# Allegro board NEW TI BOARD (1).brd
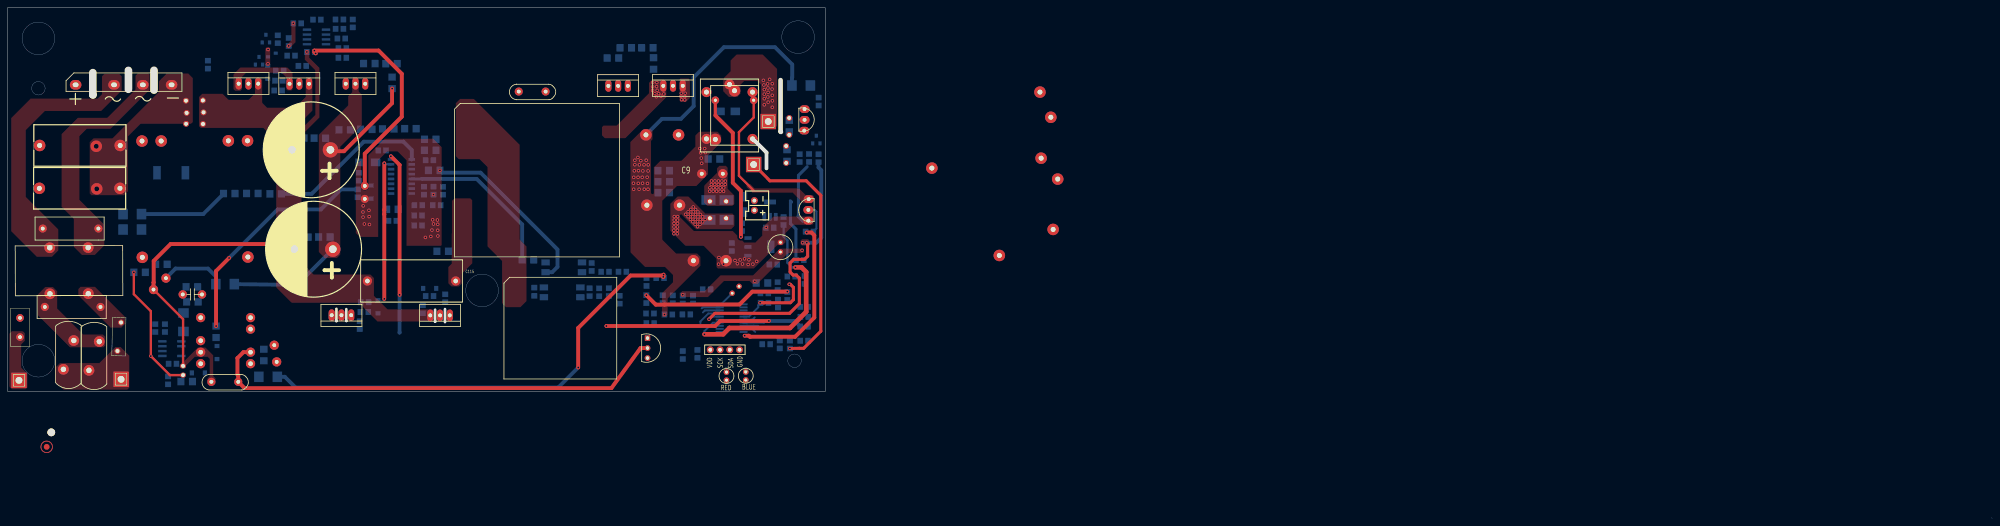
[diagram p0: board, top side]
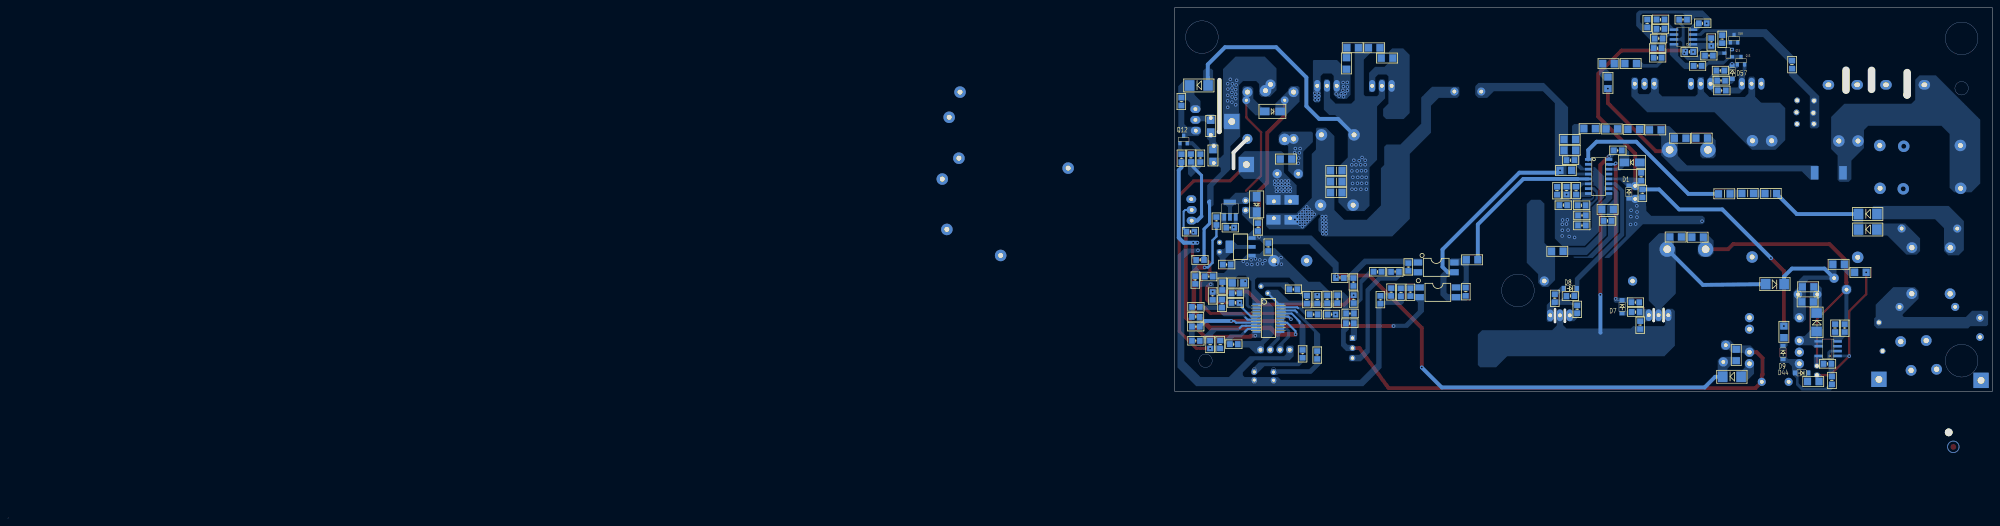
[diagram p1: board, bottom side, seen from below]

Outline 517.07 x 133.07 mm; copper layers: TOP, BOTTOM. Coordinates in mm from the lower left corner of the outline.
Outline path: circle c8,125.07 r4.25 ; circle c8,112.07 r1.75 ; circle c8,41.07 r4.25 ; circle c123.6,59.39 r4.25 ; circle c187.25,38.82 r0.5 ; circle c187.25,35.6 r0.5 ; circle c192.28,38.82 r0.5 ; circle c192.28,35.62 r0.5 ; circle c205,41.07 r1.75 ; circle c205.93,125.4 r4.25 ; 0,133.07 0,33.07 213,33.07 213,133.07 0,133.07 ; 0,133.07 0,33.07 213,33.07 213,133.07 3.74,133.07 3.74,133.07 0,133.07 ; 22.19,116.13 22.19,110.36 22.21,110.34 ; 31.46,116.71 31.46,111.81 ; 38.12,116.75 38.12,111.59 ; 85.66,54.59 85.66,51.41 85.65,51.4 ; 88.23,54.5 88.23,51.46 88.21,51.44 ; 111.37,54.36 111.37,51.26 111.36,51.25 ; 113.94,54.51 113.94,51.15 ; 194.4,98.48 194.54,98.48 197.7,95.32 197.7,91.21 ; 201.36,114.18 201.36,100.8 201.46,100.7 ; 517.07,0 516.79,0.15

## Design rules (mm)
constraint set DEFAULT: min track width 0.127

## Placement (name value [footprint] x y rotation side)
BR1  GBU1010/1000V/10A  [GBI25M]  17.71 112.97 0 top
C4  1nF/250V/1206  [1206ERD]  159.59 122.62 0 bottom
C5  1000uF/80V/TH  [CAP8_5MM18_5]  166.29 99.92 0 top
C6  1000uF/80V/TH  [CAP8_5MM18_5]  166.53 81.6 0 top
C7  2.2uf/450v  [CAP2_4MM5]  45.69 38.53 0 top
C9  100uF/100V/TH  [CAP5_5MM10_5MM]  183.58 89.79 0 top
C10  100nF/100V/0805  [1206ERD]  182.57 93.63 0 bottom
C14  1nF/250V/1206  [1206ERD]  168.11 122.62 180 bottom
C17  100uF/63V/TH  [CAP3_4MM8_5]  93.04 84.93 90 top
C19  0.47uF/50V/0805  [0805ERD]  97.59 95.88 180 bottom
C21  0805  [0805ERD]  156.63 58.94 90 bottom
C24  10nF/25V/0805  [0805ERD]  109.92 93.33 180 bottom
C25  1uF/50V/0805  [0805ERD]  91.18 84.71 270 bottom
C26  1nF/50V/1206  [0805ERD#2]  137.19 59.07 270 bottom
C30  100nF/100V/0805  [0805ERD]  170.65 57.14 270 bottom
C31  100nF/100V/0805  [0805ERD]  178.56 57.02 270 bottom
C32  10uF/1206  [C1206]  195.08 61.34 0 bottom
C33  100nF/0805  [0805ERD]  197.12 58.67 0 bottom
C34  100nF/100V/0805  [0805ERD]  197.16 56.15 0 bottom
C35  100nF/100V/0805  [0805ERD]  207.53 52.49 0 bottom
C36  100nF/100V/0805  [0805ERD]  207.49 49.97 0 bottom
C37  100nF/0805  [0805ERD]  197.64 45.38 180 bottom
C51  470uF/6.3V/TH  [CAP_2_5MM_6_5MM]  201.33 69.41 90 top
C52  100nF/100V/0805  [0805ERD]  199.5 66.13 180 bottom
C53  100nF/100V/0805  [0805ERD]  188.65 70.72 270 bottom
C55  100nF/50V/0805  [0805ERD]  155.61 64.23 0 bottom
C56  100nF/1KV/TH  [1206ERD]  111.88 69.6 0 bottom
C60  680nF 630V  [MPC_21MM_22MM]  8.32 97.16 0 top
C61  680nF/630V  [MPC_21MM_22MM]  8.25 86 0 top
C64  0805 472pF 50V  [0805ERD]  86.9 125.03 0 bottom
C81  220uF 450V  [CAP_10MM_25MM_1KW]  84.08 96.03 180 top
C82  220uF 450V  [CAP_10MM_25MM_1KW]  84.7 70.13 180 top
C106  0805 104pF 50V  [0805ERD]  73.23 124.15 270 bottom
C110  222/ I KV  [CAPY5MMPITCH]  50.62 58.35 180 top
C112  10uf/63V  [CAP4_4MM8_5]  69.77 42.94 98.3 top
C113  222/ I KV  [CAPY7MMPITCH]  53.07 35.57 0 top
C114  4.5uF450V  [CAP4_4MM8_5]  39.61 61.1 222.6 top
C115  100nF/1KV/TH  [BOXCAP_23MM]  116.73 61.85 180 top
C116  1nF/50V/0805  [0805ERD]  100.27 77.52 180 bottom
C117  1nF/50V/0805  [0805ERD]  106.91 76.32 0 bottom
C118  1nF/50V/0805  [0805ERD]  111.77 81.59 0 bottom
C121  22nF 500V  [0805ERD]  70.37 124.88 270 bottom
C122  22nF 500V  [0805ERD]  80.59 129.95 180 bottom
C123  22nF 500V  [0805ERD]  86.43 127.55 0 bottom
C124  22nF 500V  [0805ERD]  89.91 128.99 270 bottom
C125  22nF 500V  [0805ERD]  78.95 121.53 0 bottom
C126  1nF/50V/0805  [0805ERD]  113.41 85.39 270 bottom
C127  1000uF/80V/TH  [CAP8_5MM18_5]  178.66 67.13 0 top
CX1  0.22uF 275V  [CAPBOX14_5MMNEW]  24.18 55.09 180 top
CX2  NC  [CAPBOX14_5MMNEW]  23.63 75.52 180 top
CY3  2K2uF/250V/TH  [CAPY7MMPITCH]  133.15 111.22 0 top
D1  BZT52C16V/SOD-123  [DIODE_SOD123]  94.69 86.73 270 bottom
D2  M7  [DIODE_SMAF]  185.57 106.04 0 bottom
D3  ES1J  [DIODE_SMA]  34.87 79.28 180 bottom
D4  ES1J  [DIODE_SMA]  34.87 75.25 180 bottom
D5  MUR2040CT  [TO220AB_ERD]  156.5 112.69 0 top
D6  MUR2040CT  [TO220AB_ERD]  170.8 112.7 0 top
D7  1N4148/SOD-123  [DIODE_SOD123]  96.46 56.84 270 bottom
D8  1N4148/SOD-123  [DIODE_SOD123]  108.24 59.92 0 bottom
D9  RS1M  [DIODE_SOD123]  54.54 44.9 270 bottom
D12  SS34  [DIODE_SMAF]  95.85 92.75 180 bottom
D15  ES1J  [DIODE_SMAF]  191.67 79.81 90 bottom
D16  LED-RED  [LED2_1MM4_0MM]  187.27 38.1 270 top
D17  LED-BLUE  [LED2_1MM4_0MM]  192.3 38.14 270 top
D28  MUR2060CT (20A 600V  [TO220AB_ERD]  88.07 113.25 0 top
D30  DIODE  [DIODE_SMA]  209.12 112.8 180 bottom
D43  UF4007  [DIODE_SMA]  45.79 53.5 270 bottom
D44  UF4007  [DIODE_SOD123]  47.98 37.9 0 bottom
D47  UF4007  [DIODE_SMA]  54.24 61.03 0 bottom
D50  UF4007  [DIODE_SMA]  70.24 36.89 180 bottom
D54  -  [ES5J]  46.51 90.04 270 bottom
D57  UF4007  [DIODE_SOD123]  67.76 117.93 270 bottom
D58  SB80-09  [IC_SOT23_N]  67.28 126 180 bottom
F1  FUSE/5A  [FUSE_BOX_5MM]  3.22 47.23 90 top
FAN  CN3  [1X2_BERGESTICK]  194.55 80.26 90 top
ISO1  OPTO ISOLATOR-A  [SMD_OPTO_AY]  149.2 60.17 180 bottom
ISO2  OPTO ISOLATOR-A  [SMD_OPTO_AY]  149.64 66.68 180 bottom
J2  CON3  [4PIN_CON]  183.06 43.92 0 top
K1  RELAY_SPDT_1A  [RELAY_1]  189.37 111.45 270 top
K2  RELAY_SPDT_1A  [RELAY_HF3FF]  182.06 111.07 270 top
L  T POINT A  [AC_INPUT]  2.94 35.95 0 top
L3  PQ4040  [TX_PQ32_20_PIN12]  35.08 68.02 90.2 top
L7  PQ_2625  [PQ_2625_A]  131.29 60.86 0 top
LF1  LFC-20mH  [LF_T27]  20.96 70.55 180.2 top
N  T POINT A  [AC_INPUT]  29.55 36.22 0 top
NOREF  -  [unnamed]  11.36 22.4 0 top
NOREF#2  -  [#2]  213 33.07 90 top
NOREF#3  -  [#2]  0 133.07 0 top
NOREF#4  -  [unnamed#3]  10.16 18.63 0 top
NTC  SCK 202R0  [NTC_17D_7_5MM_PITCH]  17.22 38.83 90 top
NTC3  NTC 10K  [NTC_17D_7_5MM_PITCH]  23.87 38.56 90 top
PU1  SOT_89TR  [SOT223]  192.87 68.44 90 bottom
Q  USS25660  [SOIC16NEW]  105.28 93.52 270 bottom
Q1  Tr8050D  [TRANSISTOR_3PIN]  208.6 80.37 180 top
Q2  WSJM65R099DX  [TO220AB_ERD]  60.19 113.26 0 top
Q3  80R280P7  [TO220AB_ERD]  89.5 52.93 180 top
Q4  80R280P7  [TO220AB_ERD]  115.18 52.89 180 top
Q5  2SCR372P5  [SOT_89TR]  198.62 78.97 180 bottom
Q11  2N1132  [TRANSISTOR_3PIN]  207.62 103.83 0 top
Q12  Tr8050D  [IC_SOT23_N]  210.69 99.71 180 bottom
Q13  2N1132  [IC_SOT23_N]  65.49 120.25 180 bottom
Q14  WSJM65R099DX  [TO220AB_ERD]  73.44 113.23 0 top
Q15  Tr8050D  [IC_SOT23_N]  69.83 121.21 90 bottom
R2  2.2M 5% 1206  [R1206]  65.18 84.66 180 bottom
R3  2.2M 5% 1206  [R1206]  59.18 84.62 180 bottom
R4  4.7M 5% 1206  [R1206]  71.28 84.55 180 bottom
R5  2.2K/0805  [0805ERD]  208.88 74.71 0 bottom
R6  0R/1206  [1206ERD]  86.36 101.23 0 bottom
R7  0R/1206  [1206ERD]  91.99 101.36 0 bottom
R9  30/1206  [1206ERD]  156.24 119.95 0 bottom
R10  2.2M/1206  [1206ERD]  97.71 101.47 0 bottom
R11  0.33R/2W/TH  [VERTICAL]  182.96 80.39 270 top
R12  10R/0805  [0805ERD]  93.02 56.31 180 bottom
R13  10K2  [0805ERD]  40.97 49.6 270 bottom
R14  0.33R/2W/TH  [VERTICAL]  187.18 80.39 90 top
R15  2.2M/1206  [1206ERD]  103.47 101.54 0 bottom
R16  10K  [0805ERD]  91.74 50.37 270 bottom
R17  4.7M 5% 1206  [1206ERD]  92.77 118.5 0 bottom
R18  220K/1206  [1206ERD]  108.63 95.91 0 bottom
R19  68K/1206  [1206ERD]  108.65 98.76 0 bottom
R21  30/1206  [1206ERD]  168.27 117.08 90 bottom
R22  10R/0805  [0805ERD]  109.91 57.93 0 bottom
R23  10K/0805  [0805ERD]  108.15 54.5 270 bottom
R25  2.2E/1206  [1206ERD]  54.3 47.16 90 bottom
R29  0805  [0805R]  159.43 56.93 90 bottom
R30  2.2K/0805  [0805R]  154.1 58.89 90 bottom
R34  2.2K/0805  [0805ERD]  151.61 58.96 270 bottom
R39  0R/0805  [0805ERD]  191.32 75.86 90 bottom
R40  0R/1206  [1206ERD]  134.1 67.37 0 bottom
R41  4.7K/0805  [0805ERD]  202.15 77.5 270 bottom
R42  10K/805  [0805ERD]  198.58 75.75 180 bottom
R43  75K/0805  [0805R]  172.12 53.11 0 bottom
R44  0R/0805  [0805R]  176.79 53.15 0 bottom
R45  3.6K/0805  [0805R]  173.29 57.1 270 bottom
R46  10K/0805  [0805R]  182.13 59.67 180 bottom
R47  10K/0805  [0805R]  175.89 56.99 90 bottom
R48  560R/0805  [0805R]  175.9 42.58 270 bottom
R49  75K/0805  [0805R]  206.38 67.32 0 bottom
R50  1k/0805  [0805R]  207.65 62.14 270 bottom
R51  560R/0805  [0805R]  179.71 42.88 270 bottom
R52  3.6K/0805  [0805R]  204.11 63.03 0 bottom
R53  75K/0805  [0805R]  203.13 57.98 270 bottom
R54  3.6K/0805  [0805R]  200.62 60.55 270 bottom
R55  0R/0805  [0805R]  200.69 55.94 90 bottom
R56  220K/0805  [0805R]  207.53 55.11 180 bottom
R57  33K/0805  [0805R]  207.52 46.26 180 bottom
R58  27K/0805  [0805R]  203.79 45.25 90 bottom
R59  10K/0805  [0805R]  201.16 45.28 90 bottom
R106  3.3k  [0805ERD]  87.22 122.51 180 bottom
R127  2W 1% 0.22E  [VERTICAL]  48.65 108.87 0.9 top
R135  10K/0805  [0805ERD]  169.96 62.63 0 bottom
R137  10K/0805  [0805ERD]  152.16 65.47 90 bottom
R138  75K/0805  [0805ERD]  166.39 57.09 90 bottom
R139  R  [0805ERD]  167.43 50.84 180 bottom
R142  2.7K/805  [0805ERD]  167.37 53.39 180 bottom
R144  R  [0805ERD]  166.45 61.56 90 bottom
R145  10K/1206  [R1206]  172.38 87.72 180 bottom
R146  10K/1206  [R1206]  172.38 84.88 180 bottom
R147  10K/1206  [R1206]  172.38 90.62 180 bottom
R148  10k  [0805ERD]  160.19 64.26 180 bottom
R149  0.33R/2W/TH  [2512]  187.28 77.78 90 bottom
R150  0.33R/2W/TH  [2512]  182.59 77.78 90 bottom
R152  39K  [1206ERD]  203.63 103.66 270 bottom
R153  39K  [1206ERD]  203.05 93.1 90 bottom
R154  1k/0805  [0805ERD]  211.28 108.58 90 bottom
R155  39K  [0805ERD]  206.34 93.9 270 bottom
R156  39K  [0805ERD]  211.26 93.82 90 bottom
R157  39K  [0805ERD]  208.78 93.93 270 bottom
R158  0.33R/2W/TH  [VERTICAL]  203.63 102.12 90 top
R159  0.33R/2W/TH  [VERTICAL]  202.83 94.8 270.1 top
R166  15E 1% 0805  [0805ERD]  75.48 128.99 180 bottom
R170  100K  [1206ERD]  49.58 56.39 180 bottom
R171  100K  [1206ERD]  49.43 60.31 180 bottom
R172  10K2  [1206ERD]  38.6 66.2 0 bottom
R173  39K 1% 0805  [1206ERD]  75.33 73.27 0 bottom
R174  10K2  [1206ERD]  32.92 64.1 0 bottom
R176  10K2  [0805ERD]  42.97 40.26 180 bottom
R177  10K2  [0805ERD]  38.45 49.6 270 bottom
R179  10K2  [1206ERD]  66.73 44.01 270 bottom
R180  10K2  [0805ERD]  41.79 35.97 270 bottom
R181  10K2  [1206ERD]  45.2 35.65 0 bottom
R187  2.2M/1206  [0805ERD]  107.02 81.57 180 bottom
R188  68K/1206  [0805ERD]  106.9 78.94 0 bottom
R189  2.2M/1206  [0805ERD]  108.46 85.36 90 bottom
R190  68K/1206  [0805ERD]  110.93 85.42 270 bottom
R191  2.2M/1206  [1206ERD]  101.69 80.52 180 bottom
R196  10R/0805  [0805ERD]  92.95 53.77 180 bottom
R197  10R/0805  [0805ERD]  113.99 57.38 270 bottom
R198  10R/0805  [0805ERD]  91.5 88.99 90 bottom
R200  10K  1% 0805  [0805ERD]  76.74 117.9 0 bottom
R202  2.2M 5% 1206  [1206ERD]  100.15 114.93 270 bottom
R203  0E  5% 0805  [0805ERD]  52.17 118.25 270 bottom
R204  2.2M 5% 1206  [1206ERD]  98.54 118.48 0 bottom
R205  10K  1% 0805  [0805ERD]  86.46 129.99 180 bottom
R206  10K  1% 0805  [0805ERD]  70.5 111.48 180 bottom
R207  2W 1% 0.1E  [VERTICAL]  48.69 102.78 359.4 top
R208  2W 1% 0.05E  [VERTICAL]  48.83 105.72 181.8 top
R209  39K 1% 0805  [0805ERD]  87.22 120.02 180 bottom
R210  10K  1% 0805  [0805ERD]  70.89 116.67 180 bottom
R211  10K  1% 0805  [0805ERD]  70.68 114.05 180 bottom
R212  10K  1% 0805  [0805ERD]  73.8 120.57 0 bottom
R214  2.2M/1206  [1206ERD]  109.67 90.68 0 bottom
R216  39K 1% 0805  [1206ERD]  81.06 73.31 0 bottom
R217  39K 1% 0805  [1206ERD]  79.88 99.06 0 bottom
R218  39K 1% 0805  [1206ERD]  74.26 99.09 0 bottom
RV1  D14/511K  [MOV15D7_5P]  30.81 52.31 269 top
T2  TRANSFORMER FLAT COMPACT  [TX_17X6X8]  50.34 40.28 0 top
T3  PQ_4040  [PQ_40X40]  118.91 105.63 0 top
U2  HT45F  [NSOP_20PIN]  191.71 55.77 270 bottom
U4  TL431  [TO-92_TL431]  166.7 46.97 270 top
U6  UCC28180  [SOIC8]  80.46 125.43 0 bottom
U7  DAP021B1  [SOIC7_ERD]  42.78 44.21 0 bottom
UNK10K_NTC  10K_NTC  [NTC]  190.56 60.46 225 top
UNK+VE  TEST POINT  [AC_INPUT]  198.16 103.4 0 top
UNK-VE  TEST POINT  [AC_INPUT]  194.35 92.2 0 top

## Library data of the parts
BR1 = BRIDGE_2
C4 C10 C14 C19 C21 C24-C26 C30-C37 C52 C53 C55 C56 C60 C61 C64 C106 C110 C113 C115-C118 C121-C126 CX1 CX2 CY3 = CAP NP
C5 C6 C9 C81 C82 C127 = CAP POL
C7 = CAP
C17 = CAP POL_3
C51 = CAP POL_8
C112 = CAP_5
C114 = CAP_4
D1 = DIODE ZENER_0
D2-D4 D12 D15 D54 = DIODE
D5 D6 = SB80-09_0
D7 = DIODE 34/DD_0
D8 = DIODE 34/DD_1
D9 = DIODE_17
D16 D17 = LED
D28 = DIODE_11
D30 = DIODE_7
D43 = DIODE_16
D44 D57 = DIODE_18
D47 = DIODE_14
D50 = DIODE_1
D58 = SB80-09_1
F1 = FUSE
FAN = connector_smal_1
ISO1 ISO2 = OPTO ISOLATOR-A_0
J2 = CON3_1
K1 K2 = RELAY_SPDT_1
L N = T POINT A
L3 = TRAN_HM31_6
L7 = TRAN_HM31_7
LF1 = TRANSFORMER_2
NTC NTC3 RV1 UNK10K_NTC = VARISTOR
PU1 = AME1117_1
Q = ICL232_6
Q1 = NPN BCE_0
Q2 = MOSFET_EN_SGD_0
Q3 Q4 = MPF4150_1
Q5 = NPN BCE_5
Q11 Q13 = 2N1132_1
Q12 Q15 = NPN BCE_2
Q14 = MOSFET_EN_SGD_1
R2-R4 R17 R106 R127 R135 R137-R139 R142 R144 R148 R166 R173 R200 R202-R212 R216-R218 = R
R5 = RESISTOR_4
R6 R7 R9-R16 R18 R19 R21-R23 R25 R29 R30 R34 R39-R59 R145-R147 R149 R150 R154 R158 R159 R170-R172 R174 R176 R177 R179-R181 R187-R191 R196-R198 R214 = RESISTOR
R152 R153 R155-R157 = RESISTOR_2
T2 = TRANSFORMER FLAT COMPACT_1
T3 = TRANSFORMER POWER_6
U2 = IBM0118160/SO50_1
U4 = TL431_0
U6 = ICC03_1
U7 = ICC03_3
UNK+VE UNK-VE = TEST POINT

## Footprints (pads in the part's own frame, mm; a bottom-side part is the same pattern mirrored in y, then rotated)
1X2_BERGESTICK
  round 1.8 hole 1: 1(0,0) 2(2.54,0)
4PIN_CON
  round 1.8 hole 1: 1(0,0) 2(2.54,0) 3(5.08,0) 4(7.62,0)
0805ERD
  rect 1.45x1.55 smd: 1(-1,0) 2(1.05,0)
0805ERD#2
  rect 1.45x1.55 smd: 1(-1.051,-0.006) 2(1.079,-0.006)
0805R
  rect 1.45x1.55 smd: 1(-1,0) 2(1.05,0)
1206ERD
  rect 1.85x1.95 smd: 1(-0.05,0) 2(2.95,0)
2512
  rect 2.5x3.7 smd: 1(0,0) 2(5.2,0)
AC_INPUT
  rect 4x4 hole 1.8: 1(0,0)
BOXCAP_23MM
  round 2.4 hole 1.2: 1(0,0) 2(23,0)
C1206
  rect 1.85x1.95 smd: 1(-0.05,0) 2(2.95,0)
CAP2_4MM5
  oval 1.5x1.3 hole 1 unplated: (0,1.19) (0,-1.21)
CAP3_4MM8_5
  round 2.1 hole 1: 1(-1.7,0) 2(1.7,0)
CAP4_4MM8_5
  round 2.4 hole 1 unplated: (-2.2,0) (2.2,0)
CAP5_5MM10_5MM
  round 2.4 hole 1: 1(-2.75,0) 2(2.75,0)
CAP8_5MM18_5
  round 3 hole 1.3: 1(0,0) 2(8.5,0)
CAP_2_5MM_6_5MM
  round 1.4 hole 0.7: 1(0,0) 2(2.5,0)
CAP_10MM_25MM_1KW
  round 4 hole 2: 1(0,0) 2(10,0)
CAPBOX14_5MMNEW
  round 2.1 hole 1: 1(0,0) 2(14.5,0)
CAPY5MMPITCH
  round 2.201 hole 1: 1(0,0) 2(5,0)
CAPY7MMPITCH
  round 2.1 hole 1: 1(0,0) 2(7,0)
DIODE_SMA
  rect 2.5x2.752 smd: 1(0,0) 2(4.8,0)
DIODE_SMAF
  rect 2.5x2 smd: 1(0,0) 2(4,0)
DIODE_SOD123
  rect 1.1x1.3 smd: 1(3.4,0) 2(0,0)
ES5J
  rect 3.5x2 smd: 1(0.002,0.219) 2(0.002,7.61)
FUSE_BOX_5MM
  round 2 hole 1: 1(0,0) 2(5,0)
GBI25M
  oval 3x2.5 hole 1.5x1.2: 1(0,0) 2(10,0) 3(17.5,0) 4(25,0)
IC_SOT23_N
  rect 0.85x1.05 smd: 1(-0.95,-2) 2(0.95,-2) 3(0,0)
LED2_1MM4_0MM
  round 1.5 hole 0.8: 1(0,0) 2(2.1,0)
LF_T27
  round 2.8 hole 1.4: 1(0,12) 2(10,0) 3(0,0) 4(10,12)
MOV15D7_5P
  round 1.524 hole 1: 1(1.296,-1.252) 2(8.751,-2.054)
MPC_21MM_22MM
  round 3 hole 1.3: 1(0,0) 2(21,0)
NSOP_20PIN
  rect 0.5x2.1 smd: 1(0,0) 2(0.8,0) 3(1.6,0) 4(2.4,0) 5(3.2,0) 6(4,0) 7(4.8,0) 8(5.6,0) 9(6.4,0) 10(7.2,0) 11(7.2,6.2) 12(6.4,6.2) 13(5.6,6.2) 14(4.8,6.2) 15(4,6.2) 16(3.2,6.2) 17(2.4,6.2) 18(1.6,6.2) 19(0.8,6.2) 20(0,6.2)
NTC
  round 1.4 hole 0.7: 1(0,0) 2(2.54,0)
NTC_17D_7_5MM_PITCH
  round 2.8 hole 1.4: 1(0,2.7) 2(7.5,0)
PQ_40X40
  round 0 hole 1.4: 1(0,0) 2(0,-5) 3(0,-10) 4(0,-25) 5(0,-30) 6(0,-35) 7(38,-35) 8(135.804,-6.389) 9(38,-25) 10(38,-10) 11(38,-5) 12(38,0)
PQ_2625_A
  round 0 hole 1.2: 1(0,0) 2(0,-3.8) 3(113.607,20.681) 4(0,-15) 5(0,-18.8) 6(136.327,2.062) 7(25.4,-22.6) 8(113.899,-0.014) 9(124.164,18.369) 10(25.4,-7.6) 11(120.975,27.992) 12(112.554,10.215)
R1206
  rect 1.85x1.95 smd: 1(-0.05,0) 2(2.95,0)
RELAY_1
  round 2 hole 0.8: 1(2.5,-5) 3(2.5,5)
  round 3 hole 1.3: 2(0,0) 4(12.7,-5) 5(20.184,51.414)
RELAY_HF3FF
  round 2.6 hole 1.3: 1(0,0) 2(-2,6) 3(0,12) 4(12.2,0) 5(12.2,12)
SMD_OPTO_AY
  rect 2.2x1.6 smd: 1(0,0) 2(0,-2.54) 3(9.5,-2.54) 4(9.5,0)
SOIC7_ERD
  rect 2.2x0.64 smd: 1(-2.477,1.905) 2(-2.477,0.635) 3(-2.477,-0.635) 4(-2.477,-1.905) 5(2.477,-1.905) 6(2.477,-0.635) 7(2.477,1.905)
SOIC8
  rect 2.2x0.64 smd: 1(-2.477,1.905) 2(-2.477,0.635) 3(-2.477,-0.635) 4(-2.477,-1.905) 5(2.477,-1.905) 6(2.477,-0.635) 7(2.477,0.635) 8(2.477,1.905)
SOIC16NEW
  rect 0.7x1.7 smd: 1(0,0) 2(1.27,0) 3(2.54,0) 4(3.81,0) 5(5.08,0) 6(6.35,0) 7(7.62,0) 8(8.89,0) 9(8.89,5.4) 10(7.62,5.4) 11(6.35,5.4) 12(5.08,5.4) 13(3.81,5.4) 14(2.54,5.4) 15(1.27,5.4) 16(0,5.4)
SOT223
  rect 0.95x1.87 smd: 1(0,0) 2(2.3,0) 3(4.6,0)
  rect 3.25x1.87 smd: 4(2.3,5.95)
SOT_89TR
  rect 0.98x2 smd: 1(-1.5,-0.4) 2(0,-0.4) 3(1.5,-0.4)
  rect 3.1x1.26 smd: 4(0,3.45)
TO220AB_ERD
  oval 1.6x3.048 hole 1.016: 1(0,0) 2(2.54,0) 3(5.08,0)
TO-92_TL431
  rect 1.4x1.4 hole 0.9: 1(0,0)
  round 1.5 hole 0.9: 2(2.6,0) 3(5.2,0)
TRANSISTOR_3PIN
  oval 2.6x2 hole 1: 1(0,2.8) 2(0,0) 3(-0.1,-2.8)
TX_17X6X8
  round 2.4 hole 1.2 unplated: (-0.061,12.012) (-0.061,6.012) (-0.061,3.012) (-0.061,0.012) (12.939,12.012) (12.939,9.012) (12.939,3.012) (12.939,0.012)
TX_PQ32_20_PIN12
  round 3 hole 1.3: 1(0,0) 2(25.173,-234.24) 3(19.719,-238.548) 4(6.601,-237.319) 5(-0.143,-223.285) 6(0,-27.5) 7(30.3,-27.5) 8(30.3,-22.5) 9(35.827,-236.804) 10(42.396,-233.989) 11(30.3,-5) 12(30.3,0)
unnamed
  round 2 hole 2.5 unplated: (0,0)
unnamed#3
  round 1.5 smd: 1(0,0)
VERTICAL
  round 1.524 hole 1: 1(-2.2,0) 2(2.2,0)

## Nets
+5V: C32.1 C33.1 C51.1 C52.1 D16.2 D17.2 J2.1 PU1.2 PU1.4(OUT1) R29.1 R30.1 R47.2 U2.2
+12V: C53.1 D2.1(K) D50.1(K) K1.1 K2.1 PU1.3 R39.1 R135.2 R179.2
GND_SIGNAL: C5.2 C6.2 C30.1 C31.1 C32.2 C33.2 C34.2 C37.2 C51.2 C52.2 C53.2 C113.2 C127.2 CY3.2 J2.4 PU1.1 Q1.1(E) Q5.3(E) R11.2 R14.1 R42.2 R45.1 R46.2 R52.1 R54.1 R139.1 R142.1 R145.1 R146.1 R147.1 R149.1 R150.1 R155.2 R157.2 R179.1 T3.9 T3.10 U2.1(VSS) U4.2
V5P: C118.1 Q.8 R187.1 R189.1
VBAT_SENSE: K1.2(NO) K2.2(NO) R49.1 R153.1 R159.2 UNK+VE.1
VCC: C17.2 C25.1 C122.1 C125.2 D1.2(CATHODE) Q.12(VCCP) R25.2 R198.1 R212.2 U6.7
0: C17.1(2) C24.1 C25.2 C26.2 C64.2 C81.2 C82.2 C106.2 C113.1 C115.2 C116.2 C117.2 C118.2 C121.2 C122.2 C123.2 C124.2 C125.1 C126.2 CY3.1 D1.1 D58.1 D58.2 ISO1.3(EMITTER) ISO2.3(EMITTER) Q.10 Q2.3(S) Q4.3(S) Q13.2 Q14.3(S) R13.1 R18.2 R19.2 R23.2 R106.1 R127.2 R166.2 R173.1 R176.1 R177.1 R188.2 R190.2 R191.2 R206.2 R207.2 R208.1 R209.1 R214.2 R218.1 U6.1 U7.7
A: BR1.1 C60.1 C61.1 D54.2 L3.11 L3.12
BLK: C24.2 Q.3 R15.2 R18.1 R19.1
D: D9.1 D44.1 R180.2
FANOUT_PWM: R41.2 U2.14
FB_OPTO: C35.1 C36.1 ISO1.2 R34.2 U2.7
HO: D7.2(CATHODE) Q.15 R12.1
HS: C19.1 L7.4 L7.5 Q.16 Q3.3(S) Q4.2 R16.2
HV: Q.1 R4.1
HV1: C4.2 C5.1 C6.1 C9.1 C10.1 C14.2 C127.1 D5.2(3) D6.2(3) D30.2 K1.4 K2.4 R43.1 R53.1 R138.2 R144.1 R145.2 R146.2 R147.2
HV BUS: C81.1 C82.1 D28.2 D47.2 D54.1(K) Q3.2 R6.1 R202.2 R216.2 R217.2
ISEN: C9.2 C10.2 R11.1 R14.2 R58.1 R59.1 R149.2 R150.2 UNK-VE.1
ISNS: C56.1 C116.1 Q.9 R191.1
LL: C126.1 Q.6 R189.2 R190.1
LO: D8.2(CATHODE) Q.11 R22.1
PA0: J2.3 U2.11
PA2: J2.2 U2.12
RLY_CONTROL: R5.1 U2.10
SW1: R156.1 U2.16
TEST: C117.1 Q.7 R187.2 R188.1
N01891: Q3.1 R12.2 R16.1 R196.2
N02727: Q4.1 R22.2 R23.1 R197.2
N003801: R6.2 R7.1
N06052: C19.2 D12.1(K) Q.14
N16213: C26.1 ISO1.4 ISO2.4 R40.2
N21595: C21.2 ISO1.1 R30.2 R34.1
N096411: C14.1 R21.2
N116566: D15.1(K) FAN.1 R39.2
N116595: D15.2 FAN.2(-) Q5.2 Q5.4
N203221: C21.1 R29.2
N958525: R7.2 R10.1
N958531: R10.2 R15.1
N989703: D2.2 K1.3 K2.3 Q1.3
N989735: Q1.2 R5.2
N991132: C34.1 R50.2 U2.5
N991210: R49.2 R50.1 R52.2
N991406: R53.2 R54.2 R55.2
N991435: R55.1 R56.2 U2.6
N991453: C35.2 R56.1
N991579: C36.2 R57.1
N991583: R57.2 R58.2 U2.8
N991673: C37.1 R59.2 U2.9
N992059: C30.2 R43.2 R44.1 R45.2
N992164: R44.2 U2.19
N992182: C31.2 R47.1 U2.20 UNK10K_NTC.2
N992267: R48.1 U2.18
N992271: R51.1 U2.17
N995338: Q5.1 R41.1 R42.1
N1047887: C4.1 R9.2
N1057020: D5.1 D5.3 R9.1 T3.12
N1102671: D6.1 D6.3 R21.1 T3.11(N52)
N1232683: ISO2.1 R135.1 R137.2 R144.2
N1232719: R138.1 R139.2 R142.2 R148.1 U4.1(REF)
N1232753: C55.1 ISO2.2 R137.1 U4.3
N1262247: R46.1 UNK10K_NTC.1
N1271766: C55.2 R148.2
N1473058: Q11.2 R152.1 R158.2
N1473062: R152.2 R153.2 R158.1 R159.1
N1473074: D30.1(K) Q11.1(EMITTER) R154.2
N1473136: Q11.3 Q12.3 R154.1
N1473188: Q12.2(E) R155.1
N1473270: Q12.1 R156.2 R157.1
N1626311: C110.1 D47.1(K) R170.1 R171.1 R172.2
N1626403: D50.2
N1626473: D43.2 U7.5 U7.6
N1626717: R172.1 R174.2
N1626863: D44.2(K) R181.2
N1626895: R174.1 R181.1 U7.1(VDD)
N1626923: R176.2 R180.1 U7.2
N1627019: R13.2 R177.2 U7.4
N1627749: D9.2(K) R25.1
N1656581: Q.5 R40.1
N1658391: C56.2 C115.1 T3.4 T3.5 T3.6
N1674736: D7.1 R196.1
N1674945: D8.1 R197.1
N1675432: D12.2 R198.2
N1687940: D28.1 D28.3 L3.7 L3.8 Q2.2 Q14.2
N1688282: CX1.1 F1.2 LF1.1 RV1.1
N1688286: BR1.3 CX2.1 D4.2 LF1.3
N1688354: F1.1 L.1(TP)
N1688414: BR1.2(AC2) CX2.2 D3.2 LF1.2
N1688502: C106.1 U6.2
N1688572: BR1.4 C60.2 C61.2 R127.1 R203.2 R207.1 R208.2
N1688600: R202.1 R204.2
N1688684: C121.1 D58.3 R203.1 U6.3
N1688798: R166.1 U6.4
N1688806: C123.1 R205.2 U6.5
N1688834: N.1(TP) NTC.1 NTC3.1 RV1.2
N1688870: CX1.2 LF1.4 NTC.2 NTC3.2
N1688976: R17.2 R204.1
N1689262: C124.1 R205.1
N1689566: D3.1(K) D4.1(K) R3.2
N1689570: C64.1 R17.1 R106.2 R209.2 U6.6(VSENSE)
N1689690: R2.2 R3.1
N1689742: R2.1 R4.2
N1704443: Q2.1 Q14.1 R206.1 R210.1 R211.1
N1706830: Q13.3 Q15.1 R200.1
N1706858: D57.2(K) Q13.1(EMITTER) Q15.2(E) R210.2
N1706992: D57.1 R211.2
N1707045: R200.2 U6.8
N1707984: Q15.3 R212.1
N1708918: L7.1 L7.2 T3.1 T3.2 T3.3
N1744379: R217.1 R218.2
N1744386: R173.2 R216.1
N1751354: Q.4 R214.1
N1761027: C110.2 D43.1(K) R170.2 R171.2
N9920271: D16.1(CATHODE) R48.2
N9920531: D17.1(CATHODE) R51.2

Pads without a net: K1 5; K2 5; L3 1 2 3 4 5 6 9 10; L7 3 6 7 8 9 10 11 12; NOREF#4 1; Q 2 13; T3 7 8; U2 3 4 13 15; U7 3

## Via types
v1: diameter 0.9, hole 0.5, TOP to BOTTOM, 190 vias
v2: diameter 3, hole 1.3, TOP to BOTTOM, 2 vias

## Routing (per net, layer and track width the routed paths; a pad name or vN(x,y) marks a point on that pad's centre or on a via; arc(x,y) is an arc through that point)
+5V: length 0.2
  BOTTOM w0.4: R47.2 v1(175.89,58.28)
  vias: v1(194.66,61.78) v1(206.96,69.85)
+12V: length 159
  TOP w0.8: 184.37,105 K1.1
  TOP w1: v1(191.03,73.35) 191.03,85.33 188.92,87.44 188.92,100.45 184.37,105 ; v1(170.88,63.51) 170.88,63.01 v1(170.79,62.91) 170.43,63.28 162.3,63.28 148.64,49.62 v1(148.64,39.3)
  BOTTOM w1: v1(148.64,39.3) 143.45,34.11 74.97,34.11 72.19,36.89 D50.1
GND_SIGNAL: length 139.8
  TOP w1: U4.2 164.88,44.37 157.3,33.94 61.7,33.94 C113.2 60.07,37.25 59.86,37.45 59.86,41.76 61.4,43.3 63.27,43.3
  BOTTOM w0.8: 208.29,91.62 206.03,89.37 206.03,78.7
  BOTTOM w1: Q1.1 207.13,77.6 206.03,78.7
  vias: v1(173.6,75.93) v1(173.57,75.06) v1(173.56,74.15) v1(173.66,78.63) v1(173.65,77.73) v1(173.61,76.84) v1(174.49,75.93) v1(174.47,75.06) v1(174.45,74.14) v1(174.56,78.64) v1(174.54,77.72) v1(174.51,76.84) v1(176.64,79.23) v1(177.28,79.88) v1(177.28,78.59) v1(177.88,77.93) v1(177.98,80.5) v1(177.91,79.21) v1(178.51,78.57) v1(178.51,77.28) v1(178.61,81.14) v1(178.61,79.85) v1(179.14,77.91) v1(179.11,76.64) v1(179.25,80.48) v1(179.21,79.19) v1(179.74,77.28) v1(179.74,76) v1(179.84,79.84) v1(179.84,78.55) v1(180.38,76.62) v1(180.48,79.17) v1(180.44,77.91) v1(181.08,78.55) v1(181.08,77.26) v1(181.71,77.89) v1(185.21,66.24) v1(185.32,67.96) v1(186.52,66.25) v1(189.49,67.2) v1(190.11,66.35) v1(190.83,67.34) v1(191.44,66.27) v1(191.99,67.61) v1(192.92,66.14) v1(193.13,67.37) v1(194.15,66.24) v1(195.15,66.96) v1(197.63,75.81)
VBAT_SENSE: length 16.2
  BOTTOM w0.8: R49.1 205.36,75.38 203.94,76.8 203.94,82.17 204.21,82.43 203.91,82.73
  vias: v1(196.88,114.13) v1(197.03,112.92) v1(197.13,111.72) v1(197.13,110.54) v1(197.13,109.34) v1(197.13,107.76) v1(197.99,113.22) v1(198.08,112.14) v1(198.06,109.8) v1(198.12,111.01) v1(198.13,108.46) v1(198.53,114.39) v1(199.16,111.86) v1(199.19,110.23) v1(199.19,107.11) v1(199.21,113.24) v1(199.23,108.79)
VCC: length 119.4
  TOP w1: v1(80.24,121.15) 79.91,121.48 v1(79.91,121.89) 96.63,121.89 102.67,115.85 102.67,104.65 93.04,95.01 C17.2 ; v1(57.68,67.84) 54.3,64.45 v1(54.3,50.11)
  BOTTOM w1: v1(57.68,67.84) 70.34,80.49 81.59,80.49 86.8,85.71 C25.1
0: length 117.7
  TOP w0.6: 45.69,39.72 45.69,51.91 37.99,59.61
  TOP w1: 37.99,59.61 37.99,61.44 38.04,61.49 38.04,67.07 42.44,71.47 67.52,71.47 68.86,70.13 74.7,70.13
  BOTTOM w0.127: 64.54,117.55 64.54,118.25
  BOTTOM w1: 140.14,64.14 141.86,64.14 143.24,65.52 143.24,70.05 123.22,90.08 113.22,90.08 v1(112.62,90.68)
  vias: v1(73.23,123.1) v1(74.43,128.99) v1(75.62,77.44) v1(77.95,121.53) v1(92.57,79.83) v1(92.59,78.49) v1(92.62,81.43) v1(92.92,76.7) v1(94.12,80.27) v1(94.17,78.62) v1(94.25,76.57) v1(108.83,73.2) v1(110.25,73.45) v1(110.54,75.12) v1(110.72,77.78) v1(110.93,84.37) v1(110.94,76.7) v1(111.95,77.73) v1(112.05,76.63) v1(112.04,75.08) v1(112.08,73.58)
FANOUT_PWM: length 61.1
  TOP w1.2: v1(181.54,47.96) 186.4,47.96 188.04,49.61 203.82,49.61 208.04,53.83 208.04,64.19 206.84,65.39 v1(205.25,65.39)
  BOTTOM w0.5: U2.14 183.73,50.97 181.54,48.79 v1(181.54,47.96)
  BOTTOM w0.6: R41.2 202.15,73.45 203.16,72.44 203.16,66.6 204.37,65.39 v1(205.25,65.39)
FB_OPTO: length 58.5
  TOP w1: v1(198.32,51.43) 185.66,51.43 184.34,50.12 v1(155.97,50.12)
  BOTTOM w0.5: v1(198.32,51.43) 197.49,51.43 197.03,50.97 U2.7
  BOTTOM w1: C36.1 206.49,50.02 205.07,51.43 v1(198.32,51.43)
HO: length 39
  TOP w1: v1(98.12,92.5) 98.12,80.37 98.11,80.36 98.11,79.24 98.12,79.23 v1(98.12,57.19)
  BOTTOM w0.127: v1(98.12,57.19) 97.74,56.81 96.51,56.81
  BOTTOM w0.6: v1(98.12,92.5) 98.35,92.27 99.86,92.27 Q.15
HS: length 46.9
  TOP w1: v1(99.84,94.36) 102.11,92.09 v1(102.11,58.24)
  BOTTOM w1: v1(102.11,58.24) 102.11,48.43 102.06,48.39
HV: length 42.9
  BOTTOM w1: Q.1 105.28,95.97 103.1,98.14 92.78,98.14 79.19,84.55 R4.1
HV1: length 98.5
  TOP w1: v1(166.39,58.14) 168.85,55.68 171.17,55.68 171.21,55.72 190.66,55.72 194.02,59.08 v1(203.12,59.08)
  BOTTOM w1: C5.1 170.46,104.1 175.41,104.1 178.71,107.41 178.71,114.9 186.58,122.77 199.91,122.77 204.4,118.27 204.4,114.88 204.32,114.8 D30.2
  vias: v1(163.04,87.32) v1(163.09,85.76) v1(163.12,88.85) v1(163.26,90.55) v1(163.4,93.31) v1(163.4,92.14) v1(164.2,94.04) v1(164.23,88.88) v1(164.29,87.3) v1(164.35,90.58) v1(164.57,92.11) v1(164.51,85.76) v1(164.96,93.2) v1(165.32,88.88) v1(165.4,87.32) v1(165.49,90.53) v1(165.79,92.11) v1(165.85,85.76) v1(166.35,93.31) v1(166.6,88.88) v1(166.69,87.27) v1(166.88,92.11) v1(166.85,90.53) v1(166.82,85.76) v1(171.12,53.11) v1(180.35,96.36) v1(180.54,95.25) v1(180.71,93.88) v1(180.82,92.52) v1(181.6,96.36) v1(181.77,95.3)
HV BUS: length 54.7
  TOP w1: C81.1 84.45,95.66 87.61,95.66 100.15,108.2 v1(100.15,111.98)
  BOTTOM w1: D47.2 75.4,60.83 C82.1
ISEN: length 66.1
  TOP w0.8: UNK-VE.1 198.6,87.95 208.05,87.95 211.84,84.16 211.84,48.76 207.39,44.31 206.27,44.31 v1(203.79,44.25)
  vias: v1(182.9,85.24) v1(182.95,86.13) v1(183.37,87.91) v1(183.33,87.02) v1(183.81,85.25) v1(183.84,86.13) v1(184.26,87.9) v1(184.23,87.02) v1(184.76,86.13) v1(184.72,85.24) v1(185.19,87.91) v1(185.14,87.02) v1(185.65,86.13) v1(185.62,85.25) v1(186.08,87.9) v1(186.05,87.02) v1(186.56,86.11) v1(186.51,85.22) v1(186.98,87.88) v1(186.94,86.99)
RLY_CONTROL: length 44.1
  TOP w1: v1(192.01,47.59) 193.09,47.59 193.35,47.32 205.17,47.32 210.16,52.31 210.16,73.75 209.43,74.48 v1(208.16,74.48)
SW1: length 74.3
  TOP w0.8: 208.6,71.56 208.42,71.38 208.42,68.28 207.62,67.48 204.8,67.48 203.85,66.53 203.85,64.19 204.65,63.39 205.46,63.39 206.26,62.59 206.26,55.97 203.69,53.41 184.25,53.41 v1(182.73,51.89)
  BOTTOM w0.5: v1(182.73,51.89) 183.41,52.57 185.51,52.57
  BOTTOM w1: R156.1 211.26,91.42 211.97,90.71 211.97,73.12 210.66,71.82 v1(208.2,71.82) v1(207.12,71.82)
N989703: length 26.8
  TOP w0.6: K1.3 194.37,104.47 190.53,100.63 190.53,100.63 190.53,89.26 194.41,85.38
N989735: length 7.8
  BOTTOM w0.5: R5.2 209.93,74.76 210.7,75.53 210.7,79.95 210.28,80.37 Q1.2
N991132: length 19.9
  TOP w0.8: v1(196.04,56.18) 197.02,56.18 197.03,56.18 203.91,56.18 204.71,56.98 204.71,60.19 203.91,60.99 v1(203.62,60.99)
  BOTTOM w0.5: C34.1 195.56,55.55 195.56,54.99 193.14,52.57 191.71,52.57
N991435: length 3.2
  BOTTOM w0.5: 194.64,52.37 194.05,51.77 U2.6
N991583: length 4.6
  BOTTOM w0.5: U2.8 192.56,50.17 192.58,50.19 194.42,50.19 194.44,50.17 195.51,50.17 196.1,49.59
N991673: length 3.4
  BOTTOM w0.5: 191.71,49.37 193.97,49.37 194.75,48.59
N992164: length 4.8
  BOTTOM w0.5: U2.19 181.08,54.97 180.83,54.72
N992182: length 4.4
  BOTTOM w0.5: U2.20 185.88,55.77 UNK10K_NTC.2
N992267: length 4.6
  BOTTOM w0.5: 181.14,53.66 181.65,54.17 U2.18
N992271: length 6.3
  BOTTOM w0.5: 185.51,53.37 182.55,53.37 180.49,51.32 180.49,50.84
N1102671:
  vias: v1(168.06,113.58) v1(168.02,112.44) v1(168.02,111.46) v1(168.6,110.67) v1(169.07,112.52) v1(169.03,109.85) v1(169.13,113.57) v1(169.2,111.53) v1(169.61,110.67) v1(170.18,110.02) v1(170.95,110.59) v1(175.5,110.76) v1(175.45,109.97) v1(175.58,109.1) v1(176.4,109.04) v1(176.42,109.92) v1(176.51,110.78)
N1626311: length 16.9
  BOTTOM w1: D47.1 54.24,63.03 52.19,65.09 43.72,65.09 41.23,62.59
N1626895: length 34.1
  TOP w0.6: 45.69,37.32 42.26,37.32 v1(37.3,42.28) 37.3,53.97 32.87,58.41 v1(32.87,64.1)
N1656581: length 42.9
  BOTTOM w0.8: 107.99,88.44 Q.5
  BOTTOM w1: 107.99,88.44 122.19,88.44 134.05,76.59 R40.1
N1688572:
  vias: v2(23.08,96.95) v2(23.2,85.86)
N1689566: length 23.6
  BOTTOM w1: D3.1 50.95,79.28 56.23,84.57 R3.2
N1706858:
  vias: v1(67.83,122.16) v1(67.82,118.44)

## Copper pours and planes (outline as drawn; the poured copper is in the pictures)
+5V on TOP: 194.18,63.3 185.69,63.3 181.59,59.19 175.74,59.19 175.33,58.78 175.33,57.87 175.53,57.66 182.44,57.66 186.63,61.85 193.3,61.85 194.08,61.07 195.28,61.07 203.35,69.13 207.2,69.13 207.48,69.42 207.48,70.15 207.34,70.29 201.17,70.29
+5V on BOTTOM: 210.55,70.32 210.12,70.32 210.11,70.32 206.64,70.32 206.51,70.18 206.51,69.41 206.7,69.23 208.98,69.23 208.98,69.19 210.52,67.65 210.52,41.03 206.3,36.82 198.92,36.82 193.51,42.22 184.56,42.22 183.98,42.81 183.98,44.77 183.73,45.02 182.21,45.02 182.02,44.84 182.02,42.23 183.06,41.19 192.1,41.19 195.27,38.02 195.27,37.28 194.8,36.82 186.11,36.82 185.35,36.06 164.79,36.06 160.51,40.33 160.51,56.35 160.19,56.67 155.16,56.67 155.15,56.67 154.89,56.93 154.89,58.51 154.79,58.6 153.38,58.6 153.32,58.54 153.32,56.15 153.84,55.63 158.35,55.63 159.11,54.88 159.11,39.2 163.85,34.45 207.45,34.45 212.29,39.29 212.29,68.58
+5V on BOTTOM: 201.24,65.4 199.85,65.4 199.77,65.48 199.77,67.68 197.26,70.2 192.06,70.2 191.94,70.32 191.94,71.21 191.95,71.23 196.67,71.23 197.84,72.4 199.64,72.4 199.8,72.24 199.8,70.63 200.25,70.18 201.91,70.18 202.16,69.92 202.16,68.75 201.3,67.89 201.3,65.46
+5V on BOTTOM: 196.09,62.14 195.98,62.25 194.46,62.25 194.27,62.25 194.07,62.05 194.07,59.97 193.71,59.6 193.71,55.65 193.28,55.23 190.68,55.23 190.66,55.21 190.66,54.75 190.69,54.72 193.86,54.72 194.56,55.42 194.56,57.54 194.91,57.89 196.79,57.89 196.85,57.95 196.85,59.31 196.09,60.07 196.09,60.25 196.09,60.25
+12V on BOTTOM: 182.72,112.65 180.91,112.65 180.5,112.24 180.5,108.59 184.11,104.97 186.69,104.97 186.8,105.08 186.8,108.11 183.44,111.48 183.44,111.92
+12V on BOTTOM: 190.17,73.69 190.51,74.03 190.51,75.46 190.65,75.6 192.24,75.6 193.94,73.9 193.94,72.66 193.76,72.48 190.85,72.48 189.37,71.01 187.89,71.01 187.46,71.44 182.42,71.44 182.41,71.43 177.98,71.43 171.86,65.31 171.86,61.98 171.72,61.84 170.41,61.84 170.3,61.94 170.3,66.65 177.35,73.69
+12V on BOTTOM: 70.69,42.07 66.02,42.07 65.81,41.85 65.81,40.39 66.07,40.13 67.89,40.13 69.02,39 69.02,35.69 69.19,35.52 71.17,35.52 71.54,35.9 71.54,41.22
GND_SIGNAL on TOP: 174.52,83.85 177.35,83.85 181.78,79.43 188.84,79.43 188.84,79.38 189.33,78.9 189.33,76.2 188.49,75.36 184.85,75.36 179.38,75.36 175.53,79.21 175.35,79.21 174.99,78.85 174.99,78.65 178.77,74.87 185.13,74.87 185.16,74.84 188.92,74.84 191.89,71.87 194.79,71.87 196.58,73.66 196.58,73.66 196.58,75.72 199.5,78.64 209.66,78.64 209.66,78.63 209.93,78.37 209.93,76.78 209.66,76.51 204.84,76.51 202.66,74.33 202.66,71.95 201.89,71.18 200.5,71.18 194.41,65.1 185.06,65.1 184.67,65.49 184.67,67.65 181.31,71.01 176.58,71.01 172.66,74.93 172.66,82
GND_SIGNAL on BOTTOM: 70.32,46.4 68.32,46.4 66.99,45.07 63.03,45.07 61.98,44.02 61.98,42.75 62.67,42.06 63.85,42.06 64.94,43.15 67.85,43.15 68.58,43.89 70.18,43.89 70.7,44.4 70.7,46.03
GND_SIGNAL on BOTTOM: outline of 91 points within 165.89,42.94 203.91,70.37
GND_SIGNAL on BOTTOM: 171.41,80.31 171.41,99.6 173.61,101.8 175.95,101.8 176.24,101.52 176.24,96.02 177.31,94.95 177.31,83.48 181.32,79.47 188.91,79.47 188.91,79.45 189.23,79.12 189.23,76.18 188.39,75.33 181.34,75.33 181.32,75.32 179.41,75.32 175.55,79.18 175.37,79.18 175.02,78.83 175.02,78.61 175.58,78.05 175.58,74.94 174.1,73.46 156.34,73.46 151.77,78.03 151.77,94.95 146.26,100.47 146.26,107.5 144.19,109.57 139.44,109.57 138.86,110.16 138.86,112.22 139.1,112.46 145.99,112.46 148.79,109.65 148.79,102.84 154.23,97.41 157.85,97.41 158.43,96.83 158.43,92.1 159.3,91.23 159.3,81.5 163,77.8 168.89,77.8
GND_SIGNAL on BOTTOM: 209.55,93.5 209.48,93.58 205.64,93.58 205.55,93.5 205.55,92.11 208.76,88.9 209.55,89.69
GND_SIGNAL on BOTTOM: 197.59,79.59 196.67,79.59 196.61,79.53 196.61,75.11 196.77,74.95 198.2,74.95 198.27,75.02 198.27,76.44 197.63,77.08 197.63,79.56
V5P on BOTTOM: 107.64,85 104.48,85 104.43,84.95 104.43,83.96 104.63,83.76 106.91,83.76 107.3,83.37 107.3,80.87 107.45,80.72 111.37,80.72 111.49,80.84 111.49,82.24 111.25,82.48 110.15,82.48 109.27,83.36 109.28,83.37 109.28,85.03 109.18,85.13 107.77,85.13
VBAT_SENSE on TOP: 196.32,101.77 196.29,101.8 196.29,113 195.34,113.95 191.85,113.95 190.9,113 190.9,110.65 190.07,109.82 187.88,109.82 186.43,111.27 186.43,114.57 188.36,116.5 188.36,119.33 189.88,120.85 196.71,120.85 200.45,117.11 200.45,102.27 199.96,101.77
VBAT_SENSE on BOTTOM: 200.26,94.85 201.13,93.98 203.88,93.98 204.08,93.78 204.08,92.21 204.06,92.19 203.57,91.7 201.42,91.7 201.02,91.3 201.02,90.33 204.54,86.81 204.54,81.74 204.05,81.25 203.3,81.25 202.88,81.67 202.88,86.54 198.52,90.91 198.52,96.96 195.94,99.54 195.94,105.38 196.28,105.72 196.28,112.88 195.22,113.94 191.78,113.94 191.02,113.17 191.02,110.45 190.42,109.86 188.21,109.86 186.5,111.56 186.5,117.27 189.56,120.32 197.16,120.32 200.44,117.05 200.44,101.84 200.26,101.66
VCC on BOTTOM: 82.27,130.75 80.96,130.75 80.85,130.64 80.85,128.94 80.16,128.25 80.16,123.18 79.32,122.34 79.32,120.62 78.82,120.12 77,120.12 75.76,121.36 74.35,121.36 74.16,121.17 74.16,120.08 74.88,119.35 79.48,119.35 80.79,120.66 80.79,124.05 81.21,124.47 84,124.47 84.04,124.51 84.04,125.1 83.99,125.15 81.74,125.15 81.73,125.14 81.39,125.14 80.91,125.62 80.91,128.03 82.33,129.45 82.33,130.68
VCC on BOTTOM: 100.68,88.82 97.08,88.82 92.85,88.82 92.74,88.71 90.8,88.71 90.41,88.32 90.41,85.05 90.48,84.97 91.87,84.97 92.32,85.43 93.45,85.43 94.12,86.1 95.31,86.1 95.47,86.25 95.47,86.6 96.96,88.09 100.69,88.09 100.74,88.13 100.74,88.76
0 on TOP: 90.69,74.37 91.73,73.33 96.53,73.33 96.53,84.46 96.54,84.46 96.54,93.28 98.88,95.62 101.59,95.62 103.9,93.3 103.9,71.04 112.88,71.04 113.06,71.21 113.06,96.71 110.83,98.94 97.69,98.94 90.69,91.94
0 on TOP: 72.58,123.21 72.58,122.78 72.95,122.41 73.33,122.41 75.01,124.09 75.01,129.25 74.72,129.54 74.03,129.54 73.89,129.4 73.89,124.52
0 on TOP: 66.61,101.74 69.97,98.38 69.97,71.7 69.98,71.69 69.98,60.18 74,56.16 91.47,56.16 96.34,51.29 110.64,51.29 110.93,51.58 110.93,54.15 110.63,54.45 98.98,54.45 95.42,58.01 95.42,62.61 94.48,63.55 79.68,63.55 77.69,65.53 77.69,72.38 76.54,73.53 76.54,99.07 76.55,99.79 81.22,104.46 81.22,117.36 78.59,119.99 78.59,121.81 78.33,122.06 77.52,122.06 77.41,121.95 77.41,119.5 80.14,116.77 80.14,105.12 76.24,101.21 75.07,101.21 75.07,101.92 79.38,106.22 79.38,114.53 78.99,114.92 77.94,114.92 77.64,114.61 77.64,109.78 74.85,107 67.59,107 66.31,108.27 66.31,114.42 65.82,114.91 64.82,114.91 64.43,114.52 64.43,110.71 62.82,109.11 62.82,109.07 57.53,109.07 55.99,110.61 50.65,110.61 49.84,109.8 49.84,102.2 50.3,101.74
0 on TOP: 46.2,39.07 45.16,39.07 44.81,39.41 44.81,39.75 49.6,44.53 51.47,44.53 53.55,42.46 53.55,37.07 53.71,36.91 54.16,36.46 54.16,35.1 53.54,34.48 52.55,34.48 52.03,35.01 52.03,36.46 52.65,37.08 52.65,41.52 52.06,42.1 48.74,42.1 46.46,39.82 46.46,39.34
0 on BOTTOM: 110.51,54.39 109.59,54.39 109.37,54.16 107.61,54.16 107.6,54.17 107.38,53.95 107.38,52.91 108.91,51.38 110.47,51.38 110.94,51.84 110.94,53.96
0 on BOTTOM: 64.03,117.06 64.45,116.64 64.45,112.06 65.79,110.72 70.07,110.72 70.16,110.81 70.16,112.14 70.04,112.26 66.43,112.26 66.05,112.63 66.05,115.41 65.03,116.42 65.03,118.7 64.96,118.78 64.09,118.78 64.03,118.72
0 on BOTTOM: 89.18,128.67 88.87,128.36 86.83,128.36 86.75,128.27 86.75,126.86 87.22,126.38 87.22,124.12 87.49,123.85 87.49,119.29 87.54,119.25 88.88,119.25 89.06,119.43 89.06,124.58 92.77,128.29 92.77,131.62 92.04,132.35 75.44,132.35 73.54,130.44 73.54,128.45 73.8,128.19 75,128.19 75.15,128.34 75.15,130.25 75.46,130.56 77.47,130.56 78.85,129.18 80.18,129.18 80.26,129.26 80.26,131.18 80.62,131.54 91.18,131.54 91.76,130.96 91.76,129.28 91.14,128.67
0 on BOTTOM: 46.32,42.66 44.23,42.66 44.15,42.58 44.15,41.82 43.24,40.91 43.24,39.54 43.72,39.06 46.15,39.06 46.5,39.41 46.5,42.49
0 on BOTTOM: 41.69,49.84 37.76,49.84 37.5,50.1 37.5,58.22 36.72,59.01 36.72,60.34 37.25,60.88 38.73,60.88 39.3,60.3 39.3,59.08 38.54,58.32 38.54,51.95 39.16,51.33 41.68,51.33 41.76,51.26 41.76,49.91
0 on BOTTOM: 75.05,100.08 73.63,100.08 72.07,98.52 72.07,94.43 72.68,93.81 75.52,93.81 76.11,94.41 76.11,96.94 75.16,97.9 75.16,99.98
0 on BOTTOM: 79.05,123.88 71.79,123.88 71.46,124.2 71.46,124.2 71.12,124.54 65.99,124.54 65.89,124.45 65.89,123.51 65.96,123.44 69.33,123.44 69.67,123.1 71.69,123.1 72.43,122.36 75.66,122.36 77.25,120.77 78.59,120.77 78.71,120.89 78.71,122.83 79.09,123.2 79.09,123.84
0 on BOTTOM: 142.29,64.95 139.11,64.95 139.03,64.87 139.03,63.41 139.15,63.29 141.58,63.29 142.2,62.67 142.2,58.82 141.81,58.43 138.74,58.43 138.65,58.43 138.23,58.43 137.96,58.7 136.61,58.7 136.43,58.52 136.43,57.37 137.07,56.73 142.35,56.73 143.8,58.18 143.8,63.44
0 on BOTTOM: 103.52,91.54 96.71,84.72 96.7,84.72 96.34,84.37 90.47,84.37 90.2,84.1 90.2,81.28 90.15,81.23 90.15,80.12 88.85,78.82 75.45,78.82 74.92,78.28 74.92,77.19 75.46,76.64 91.02,76.64 99.81,67.86 108.92,67.86 113.97,72.91 113.97,108.18 117.08,111.29 129.88,111.29 131.61,109.56 133.92,109.56 134.71,110.35 134.71,112.62 133.87,113.45 116.83,113.45 112.74,109.37 112.74,109.36 110.52,107.15 110.52,92.67 109.39,91.54
0 on BOTTOM: 76.03,74.25 74.46,74.25 72.62,72.41 72.62,69.08 73.57,68.12 75.88,68.12 76.75,69 76.75,71.07 76.18,71.64 76.18,74.11
A on BOTTOM: 39.78,87.69 37.42,87.69 36.72,88.38 36.72,93.22 33.46,96.48 33.46,101.18 32.34,102.3 13.27,102.3 11.12,100.15 11.12,86.14 9.92,84.95 5.47,84.95 3.14,87.27 3.14,103.88 14.7,115.44 18.94,115.44 20.07,114.31 20.07,109.06 21.11,108.02 38.55,108.02 42,104.57 42,96.23 40.3,94.53 40.3,88.2
BLK on BOTTOM: 105.5,100.58 105.57,100.51 107.25,100.51 107.48,100.29 107.48,92.34 106.47,91.34 104.39,91.34 104.36,91.3 104.36,90.71 104.39,90.68 107.28,90.68 108.17,91.57 108.17,92.29 108.42,92.54 109.4,92.54 109.5,92.64 109.5,102.23 108.99,102.74 105.71,102.74 105.5,102.53
D on BOTTOM: 55.22,42.13 53.83,42.13 53.21,41.51 49.74,41.51 49.04,40.81 49.04,39.75 50.48,38.31 50.48,35.23 49.29,34.04 43.46,34.04 42.6,34.91 42.6,35.49 42.46,35.63 41.17,35.63 41.05,35.5 41.05,34.34 42.07,33.32 49.72,33.32 51.14,34.73 51.14,36.53 52.22,37.61 52.22,39.63 53.06,40.47 55.08,40.47 55.28,40.67 55.28,42.07
FB_OPTO on BOTTOM: 207.23,53.27 205.86,53.27 205.73,53.14 205.73,49.24 205.77,49.19 207.18,49.19 207.25,49.27 207.25,53.25
FB_OPTO on BOTTOM: 152.41,58.46 152.24,58.63 150.83,58.63 150.65,58.45 148.21,58.45 148.08,58.32 148.08,53.83 150.51,51.39 152.27,49.63 156.36,49.63 156.56,49.84 156.56,50.54 156.39,50.72 153.06,50.72 149.67,54.1 149.67,56.26 150.54,57.12 150.93,57.12 150.94,57.12 152.23,57.12 152.41,57.3
HO on BOTTOM: 97.08,57.51 93.71,57.51 93.29,57.1 93.29,55.66 93.39,55.56 94.7,55.56 95.32,56.18 98.33,56.18 98.64,56.49 98.64,57.38 98.36,57.66 97.63,57.66 97.48,57.51 97.08,57.51
HS on BOTTOM: 98.98,94.07 98.98,93.26 99.1,93.15 100.69,93.15 100.75,93.2 100.75,93.96 99.87,94.84 99.87,96.37 99.58,96.66 97.97,96.66 97.88,96.57 97.88,95.18
HS on BOTTOM: 85.61,50.08 85.22,50.47 85.22,54.18 84.81,54.6 83.27,54.6 82.7,54.02 82.7,44.98 85.46,42.22 126.4,42.22 129.27,39.35 133.42,39.35 134.04,39.97 134.04,47.92 132.93,49.03 123.21,49.03 123.2,49.04 114.68,49.04 113.49,50.23 113.49,54.13 113.14,54.48 112.24,54.48 111.83,54.07 111.83,50.34 110.96,49.47 101.71,49.47 94.18,49.47 93.56,50.08
HV1 on TOP: 167.62,84.73 167.86,84.49 168.03,84.49 168.03,84.49 168.15,84.49 168.35,84.69 168.35,91.47 170.03,93.15 175.51,93.15 176.77,94.41 176.77,94.43 177.2,94.86 177.2,94.88 179.17,96.86 179.17,99.79 180.13,100.74 181.96,100.74 181.96,100.74 184.92,100.74 185.9,99.76 185.9,98.05 182.46,94.61 182.46,89.65 179.42,86.61 174.38,86.61 170.56,82.79 170.56,72.57 174.12,69.01 179.61,69.01 180.48,68.14 180.48,65.83 171.94,57.28 171.94,53.01 171.45,52.52 170.72,52.52 170.46,52.78 170.46,58.65 173.34,61.52 173.34,63.41 171.73,65.01 171.73,65.01 171.23,65.51 166.05,65.51 162.26,69.3 162.26,91.46 162.22,91.5 162.22,98.03 165.63,101.44 167.55,101.44 168.01,100.98 168.01,98.76 167.62,98.37
HV1 on BOTTOM: 205.46,111.43 203.25,111.43 203.02,111.66 203.02,116.72 203.48,117.18 205.09,117.18 205.62,116.65 205.62,111.59
HV1 on BOTTOM: 167.12,61.28 165.85,61.28 165.68,61.11 165.68,57.53 165.8,57.42 167.03,57.42 167.16,57.55 167.16,61.23
HV1 on BOTTOM: 167.01,108.07 166.09,108.98 166.12,109.01 166.12,123.67 166.09,123.7 161.56,123.7 161.55,123.69 161.55,121.71 163.75,119.52 163.75,110.42 163.33,110 160.29,110 160.29,110.01 159.86,110.44 159.86,114.06 159.5,114.42 158.53,114.42 158.21,114.1 158.21,109.42 160.29,107.34 160.29,93.42 162.27,91.44 162.27,81.41 163.62,80.07 168.11,80.07 170.38,82.33 170.38,91.35 170.37,91.35 170.37,91.59 167.93,94.04 167.93,101.81 170.33,104.2 170.33,104.2 171.21,105.08 172.75,105.08 174.16,106.49 174.16,114.14 173.84,114.45 173.06,114.45 172.62,114.01 172.61,114.01 172.53,113.94 172.53,109.49 171.11,108.07
HV1 on BOTTOM: 183.45,96.95 183.75,97.25 185.3,97.25 185.96,97.9 185.96,99.82 185.01,100.77 177.38,100.77 177.02,100.4 177.02,98.05 179.52,95.55 179.52,89.11 180.15,88.49 181.34,88.49 183.45,90.6
HV BUS on TOP: 81.07,69.38 82.58,67.87 85.82,67.87 86.64,68.7 86.64,95.99 86.65,96 86.65,96.82 92.25,102.42 92.25,110.44 91.46,111.23 91.46,114.51 91.1,114.87 90.03,114.87 89.76,114.6 89.76,111.02 88.72,109.98 88.72,107.62 81.07,99.97
HV BUS on BOTTOM: 81.97,100.04 81.97,94.45 81.34,93.83 81.34,93.77 79.54,91.97 45.57,91.97 45.29,91.69 45.29,88.45 45.48,88.26 47.49,88.26 49.63,90.41 82.08,90.41 86.28,94.61 86.28,99.44 87.23,100.38 87.23,102.17 87.17,102.23 84.16,102.23
HV BUS on BOTTOM: 89.51,71.57 86.8,74.29 83.28,74.29 82.96,73.97 82.96,71.11 82.48,70.63 82.48,58.53 86.05,54.96 86.05,51.56 86.3,51.31 87.61,51.31 87.81,51.51 87.81,55.03 89.51,56.73
ISEN on TOP: 189.31,84.14 187.77,85.68 187.77,85.7 187.57,85.9 187.57,91.39 187.09,91.87 185.46,91.87 184.8,91.21 184.8,90.01 181.47,86.69 181.47,82.24 182.29,81.42 188.78,81.42 189.31,81.94
ISEN on BOTTOM: 204.51,45.03 200.57,45.03 200.41,44.87 200.41,43.6 200.49,43.52 204.53,43.52 204.57,43.55 204.57,44.96
ISEN on BOTTOM: 182.01,81.68 188.96,81.68 189.48,82.19 189.48,86.7 191.24,88.46 195.02,88.46 196.34,89.77 196.34,94.17 194.81,95.69 185.21,95.69 184.58,95.05 184.58,90.12 181.23,86.78 181.23,82.45
ISNS on BOTTOM: 100.68,85.01 99.09,85.01 99.01,84.93 99.01,84.17 99.01,84.17 99.01,83.34 100.82,81.53 100.82,78.62 100.53,78.32 100.53,73.72 105.62,68.63 112.66,68.63 112.75,68.72 112.75,70.42 112.55,70.62 105.99,70.62 101.98,74.63 101.98,78.87 102.65,79.53 102.65,81.54 100.71,83.48 100.71,84.98
LL on BOTTOM: 107.11,87.52 104.42,87.52 104.36,87.46 104.36,86.83 104.39,86.8 106.61,86.8 107.71,85.71 114.13,85.71 114.2,85.78 114.2,87.05 114.07,87.18 107.45,87.18
LO on BOTTOM: 100.72,87.53 97.94,87.53 95.9,85.49 95.9,73.66 104.52,65.04 104.53,65.04 107.58,61.99 107.58,57.8 108.17,57.21 109.25,57.21 109.25,57.21 109.61,57.21 109.64,57.25 109.64,58.66 108.77,59.54 108.77,62.61 96.96,74.42 96.96,85.23 98.56,86.83 100.67,86.83 100.75,86.91 100.75,87.51
PA0 on BOTTOM: 186.54,48.83 184.48,48.83 184.44,48.79 184.44,48.34 184.5,48.29 185.09,48.29 185.63,47.76 185.63,46.62 187.24,45 187.26,45 187.26,43.47 187.26,43.47 187.26,43.41 187.7,42.97 188.67,42.97 189.06,43.36 189.06,44.43 186.56,46.93 186.56,48.8
PA2 on BOTTOM: 186.55,49.63 183.62,49.63 182.93,48.95 182.93,47.18 184.69,45.42 184.69,43.46 185.2,42.95 185.91,42.95 186.49,43.53 186.49,44.82 183.66,47.64 183.66,48.64 184.14,49.12 186.56,49.12 186.57,49.13 186.57,49.62
RLY_CONTROL on BOTTOM: 192.74,48.83 190.72,48.83 190.62,48.74 190.62,47.23 190.77,47.08 192.92,47.08 192.99,47.16 192.99,48.58
SW1 on TOP: 208.57,72.72 206.95,72.72 206.57,72.35 206.57,71.47 206.95,71.09 208.67,71.09 208.83,71.25 208.83,72.45
TEST on BOTTOM: 106.12,86.28 103.66,86.28 102.75,85.37 102.75,83.2 104.78,81.17 104.78,76 105.22,75.55 106.54,75.55 106.68,75.7 106.68,82.26 106.56,82.39 104.28,82.39 103.35,83.31 103.35,84.82 104.1,85.57 106.13,85.57 106.15,85.59 106.15,86.25
N01891 on BOTTOM: 90.61,54.52 89.17,54.52 88.66,54.02 88.66,51.84 89.16,51.34 90.28,51.34 90.97,50.65 92.41,50.65 92.59,50.83 92.59,52.33 92.59,52.33 92.59,56.98 92.5,57.07 91.34,57.07 91.26,56.99 91.26,55.17
N02727 on BOTTOM: 109.68,56.25 107.45,56.25 107.37,56.17 107.37,54.93 107.49,54.81 108.88,54.81 109.7,55.63 113.45,55.63 114.37,54.7 114.37,51.52 114.71,51.19 115.82,51.19 116.07,51.44 116.07,55.62 114.64,57.05 112.35,57.05 111.7,57.7 111.7,58.64 111.64,58.71 110.32,58.71 110.21,58.6 110.21,56.78
N003801 on BOTTOM: 92.78,102.35 88.6,102.35 88.43,102.17 88.43,100.47 88.61,100.28 92.65,100.28 92.85,100.48 92.85,102.29
N06052 on BOTTOM: 95.77,96.68 94.6,95.52 94.6,91.83 94.72,91.72 95.8,91.72 96.91,90.61 100.68,90.61 100.75,90.67 100.75,91.31 100.7,91.35 97.85,91.35 97.07,92.13 97.07,94.83 97.28,95.04 97.28,96.6 97.2,96.68
N16213 on BOTTOM: 137.94,68.44 136.28,68.44 136.16,68.32 136.16,66.5 136.4,66.26 136.4,59.5 136.49,59.41 140.75,59.41 140.75,59.41 140.87,59.52 140.87,60.84 140.73,60.98 138.58,60.98 137.73,61.83 137.73,65.48 138.15,65.91 141.03,65.91 141.04,65.89 141.25,66.1 141.25,67.47 140.96,67.76 138.62,67.76
N21595 on BOTTOM: 157.34,60.76 150.57,60.76 150.36,60.96 148.2,60.96 148.09,60.85 148.09,59.5 148.24,59.35 150.73,59.35 150.84,59.24 157.29,59.24 157.41,59.36 157.41,60.68
N096411 on BOTTOM: 167.26,123.76 169.08,123.76 169.26,123.58 169.26,119.11 169.24,119.1 167.3,119.1 167.29,119.11 167.29,121.67 167.22,121.73 167.22,123.71
N116566 on BOTTOM: 195.5,80.95 195.28,81.17 190.86,81.17 190.54,80.85 190.54,76.27 190.64,76.17 192.55,76.17 195.5,79.12
N116595 on BOTTOM: 197.71,81.55 198.09,81.17 198.09,77.61 198.16,77.54 199.07,77.54 199.13,77.61 199.13,81.05 199.66,81.58 200.24,81.58 200.44,81.78 200.44,83.13 200.27,83.3 198.72,83.3 197.19,84.82 194.39,84.82 194.13,85.08 190.8,85.08 190.68,84.95 190.68,82.71 190.85,82.54 193.36,82.54 193.99,81.91 197.34,81.91 197.69,81.55
N203221 on BOTTOM: 160.15,58.73 156,58.73 155.86,58.6 155.86,57.34 155.97,57.24 160.06,57.24 160.22,57.4 160.22,58.67
N958525 on BOTTOM: 98.53,102.47 94.2,102.47 94,102.27 94,100.54 94.16,100.38 98.43,100.38 98.6,100.55 98.6,102.4
N958531 on BOTTOM: 104.27,102.53 99.85,102.53 99.72,102.41 99.72,100.58 99.83,100.48 104.2,100.48 104.33,100.61 104.33,102.46
N989703 on TOP: 209.53,82.13 207.24,82.13 204.49,84.88 193.97,84.88 192.5,86.35 192.5,87.11 193.47,87.11 194.61,85.98 206.17,85.98 207.89,84.25 209.73,84.25 209.73,84.22 210.01,83.94 210.01,82.61
N989703 on BOTTOM: 194.98,112.58 193.08,112.58 192.54,112.04 192.54,109.4 190.26,107.12 188.45,107.12 188.33,107 188.33,105.15 188.45,105.02 191.96,105.02 195.35,108.41 195.35,112.22
N991132 on BOTTOM: 206.56,61.59 203.18,61.59 202.8,61.22 202.8,60.48 202.92,60.36 202.93,60.37 207.24,60.37 207.25,60.36 208.32,60.36 208.45,60.48 208.45,61.82 206.79,61.82
N991210 on BOTTOM: 208.07,68.11 206.79,68.11 206.68,67.99 206.68,66.51 207.13,66.06 207.13,65.19 205.82,63.89 204.6,63.89 204.46,63.75 204.46,62.27 204.49,62.25 205.82,62.25 205.85,62.28 208.22,62.28 208.49,62.56 208.49,65.91 208.15,66.25 208.15,68.03
N991406 on BOTTOM: 203.85,57.69 202.57,57.69 202.56,57.69 201.93,57.69 201.49,58.13 201.49,60.05 201.3,60.24 199.89,60.24 199.83,60.18 199.83,56.42 200.03,56.22 203.86,56.22 203.92,56.29 203.92,57.61
N991435 on BOTTOM: 205.85,55.89 205.42,55.46 201.7,55.46 201.5,55.66 199.96,55.66 199.9,55.6 199.9,54.06 199.52,53.68 195.43,53.68 193.77,52.03 190.67,52.03 190.66,52.02 190.66,51.54 190.68,51.53 194.16,51.53 194.35,51.71 195.32,52.68 200.29,52.68 201.91,54.3 207.08,54.3 207.2,54.42 207.2,55.79 207.1,55.89
N991453 on BOTTOM: 209.32,55.59 209.04,55.88 207.93,55.88 207.85,55.8 207.85,51.76 207.89,51.71 209.24,51.71 209.32,51.79
N991579 on BOTTOM: 207.86,50.76 207.81,50.71 207.81,45.54 207.97,45.38 209.14,45.38 209.3,45.54 209.3,50.72 209.26,50.76
N991583 on BOTTOM: 195.67,50.43 190.68,50.43 190.66,50.4 190.66,49.94 190.68,49.92 195.21,49.92 196.37,48.77 202.13,48.77 203,47.89 203,45.67 203.08,45.59 205.69,45.59 205.8,45.49 207.12,45.49 207.22,45.59 207.22,46.98 207.13,47.08 205.92,47.08 203.58,49.42 203.57,49.42 203.26,49.74 196.35,49.74 195.75,50.34 195.75,50.35
N991673 on BOTTOM: 194.26,49.63 190.67,49.63 190.65,49.62 190.65,49.14 190.68,49.12 193.69,49.12 195.39,47.42 195.4,47.42 195.71,47.11 197.65,47.11 197.93,46.83 197.93,44.75 198.04,44.64 199.3,44.64 199.38,44.72 199.38,45.19 199.82,45.62 201.81,45.62 201.95,45.76 201.95,46.94 201.8,47.09 199.55,47.09 198.68,47.96 196.16,47.96 195.93,47.96
N992059 on BOTTOM: 171.41,56.82 169.96,56.82 169.88,56.74 169.88,55.4 169.88,55.4 170.08,55.21 171.89,55.21 172.43,54.66 172.43,52.38 172.51,52.3 176.42,52.3 176.51,52.4 176.51,53.85 176.43,53.93 174.49,53.93 174.05,54.36 174.05,56.67 173.94,56.78 171.44,56.78
